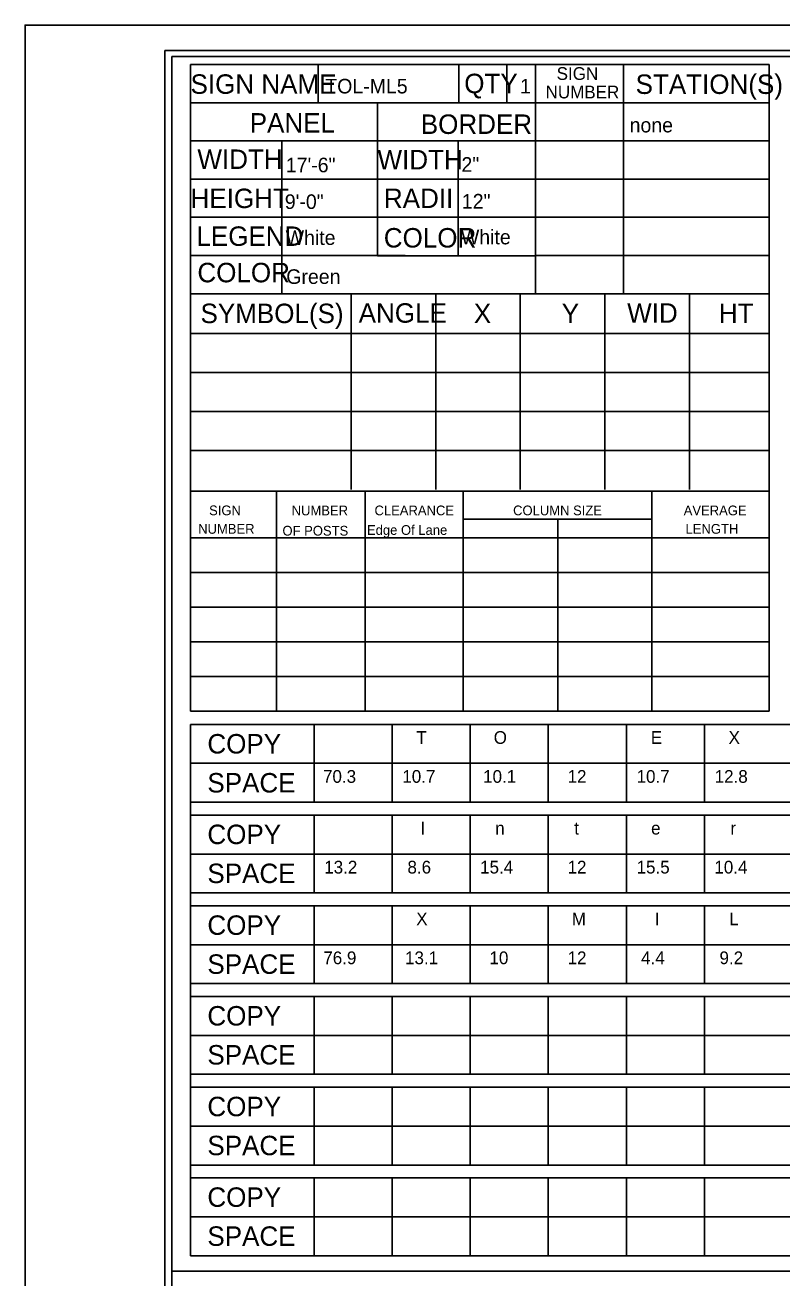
# Model space of a CAD drawing. Extents: x 122633 to 124574, y -23288 to -22025.
# Drawn here: x 122633 to 122983, y -22604 to -22025 of the extents above; entities that cross this region are included whole.
import ezdxf

# ---------------------------------------------------------------- set-up
doc = ezdxf.new("R2010")
doc.units = 0
for name, color, linetype in [('GSSign', 7, 'Continuous'), ('PlotBorder_dp', 7, 'Continuous'), ('SheetBorder_dp', 7, 'Continuous'), ('SheetLinesMisc2_dp', 7, 'Continuous'), ('TextMinor', 7, 'Continuous')]:
    doc.layers.add(name, color=color, linetype=linetype)

msp = doc.modelspace()

# ---------------------------------------------------------------- linework, layer by layer
at = {"layer": 'PlotBorder_dp'}
msp.add_lwpolyline([(122633.11, -23271.62), (124574.11, -23271.62), (124574.11, -22024.68), (122633.11, -22024.68)], close=True, dxfattribs=at)
at = {"layer": 'SheetBorder_dp'}
for q in [(124509.41, -22036.45), (122697.81, -23259.86)]:
    msp.add_line((122697.81, -22036.45), q, dxfattribs=at)
at = {"layer": 'SheetLinesMisc2_dp'}
for p, q in [((122701.01, -22039.22), (124506.26, -22039.22)), ((122701.01, -22039.22), (122701.01, -23162.98)), ((122709.67, -22342.04), (122709.67, -22042.97)), ((122709.67, -22042.97), (122977.34, -22042.97)), ((122768.68, -22042.97), (122768.68, -22060.63)), ((122833.74, -22042.97), (122833.74, -22060.63)), ((122855.97, -22042.97), (122855.97, -22060.63)), ((122869.21, -22042.97), (122869.21, -22148.96)), ((122909.94, -22042.97), (122909.94, -22148.96)), ((122977.34, -22042.97), (122977.34, -22342.04)), ((122709.67, -22060.63), (122977.34, -22060.63)), ((122796.18, -22060.63), (122796.18, -22131.48)), ((122709.67, -22078.3), (122977.34, -22078.3)), ((122751.97, -22078.3), (122751.97, -22148.96)), ((122833.51, -22078.49), (122833.51, -22131.48)), ((122709.67, -22095.97), (122977.34, -22095.97)), ((122709.67, -22113.63), (122977.34, -22113.63)), ((122709.67, -22131.3), (122808.94, -22131.3)), ((122796.18, -22131.48), (122869.21, -22131.48)), ((122869.21, -22131.3), (122977.34, -22131.3)), ((122709.67, -22148.96), (122977.34, -22148.96)), ((122784.01, -22149.31), (122784.01, -22239.5)), ((122823.12, -22149.31), (122823.12, -22239.5)), ((122862.23, -22149.31), (122862.23, -22239.5)), ((122901.34, -22149.31), (122901.34, -22239.5)), ((122940.45, -22149.31), (122940.45, -22239.5)), ((122709.73, -22167.35), (122977.34, -22167.35)), ((122709.73, -22185.39), (122977.34, -22185.39)), ((122709.73, -22203.42), (122977.34, -22203.42)), ((122709.73, -22221.46), (122977.34, -22221.46)), ((122709.67, -22240.36), (122977.34, -22240.36)), ((122749.39, -22240.36), (122749.39, -22342.04)), ((122790.45, -22240.36), (122790.45, -22342.04)), ((122835.78, -22240.36), (122835.78, -22342.04)), ((122923.07, -22240.36), (122923.07, -22342.04)), ((122835.78, -22253.29), (122923.01, -22253.29)), ((122879.6, -22253.29), (122879.6, -22342.04)), ((122709.67, -22261.92), (122977.34, -22261.92)), ((122709.67, -22277.94), (122977.34, -22277.94)), ((122709.67, -22293.97), (122977.34, -22293.97)), ((122709.67, -22309.99), (122977.34, -22309.99)), ((122709.67, -22326.01), (122977.34, -22326.01)), ((122709.67, -22342.04), (122977.34, -22342.04)), ((122709.67, -22348.2), (123597.5, -22348.2)), ((122709.67, -22594.02), (122709.67, -22348.2)), ((122766.82, -22348.2), (122766.82, -22384.27)), ((122802.94, -22348.2), (122802.94, -22384.27)), ((122839.06, -22348.2), (122839.06, -22384.27)), ((122875.17, -22348.2), (122875.17, -22384.27)), ((122911.28, -22348.2), (122911.28, -22384.27)), ((122947.4, -22348.2), (122947.4, -22384.27)), ((122709.67, -22366.23), (123597.5, -22366.23)), ((122709.67, -22384.27), (123597.5, -22384.27)), ((122709.67, -22390.15), (123597.5, -22390.15)), ((122766.82, -22390.15), (122766.82, -22426.22)), ((122802.94, -22390.15), (122802.94, -22426.22)), ((122839.06, -22390.15), (122839.06, -22426.22)), ((122875.17, -22390.15), (122875.17, -22426.22)), ((122911.28, -22390.15), (122911.28, -22426.22)), ((122947.4, -22390.15), (122947.4, -22426.22)), ((122709.67, -22408.19), (123597.5, -22408.18)), ((122709.67, -22426.22), (123597.5, -22426.22)), ((122709.67, -22432.1), (123597.5, -22432.1)), ((122766.82, -22432.1), (122766.82, -22468.17)), ((122802.94, -22432.1), (122802.94, -22468.17)), ((122839.06, -22432.1), (122839.06, -22468.17)), ((122875.17, -22432.1), (122875.17, -22468.17)), ((122911.28, -22432.1), (122911.28, -22468.17)), ((122947.4, -22432.1), (122947.4, -22468.17)), ((122709.67, -22450.14), (123597.5, -22450.14)), ((122709.67, -22468.17), (123597.5, -22468.17)), ((122709.67, -22474.05), (123597.5, -22474.05)), ((122766.82, -22474.05), (122766.82, -22510.12)), ((122802.94, -22474.05), (122802.94, -22510.12)), ((122839.06, -22474.05), (122839.06, -22510.12)), ((122875.17, -22474.05), (122875.17, -22510.12)), ((122911.28, -22474.05), (122911.28, -22510.12)), ((122947.4, -22474.05), (122947.4, -22510.12)), ((122709.67, -22492.09), (123597.5, -22492.09)), ((122709.67, -22510.12), (123597.5, -22510.12)), ((122709.67, -22516.01), (123597.5, -22516.01)), ((122766.82, -22516.01), (122766.82, -22552.08)), ((122802.94, -22516.01), (122802.94, -22552.08)), ((122839.06, -22516.01), (122839.06, -22552.08)), ((122875.17, -22516.01), (122875.17, -22552.08)), ((122911.28, -22516.01), (122911.28, -22552.08)), ((122947.4, -22516.01), (122947.4, -22552.08)), ((122709.67, -22534.04), (123597.5, -22534.04)), ((122709.67, -22552.08), (123597.5, -22552.08)), ((122709.67, -22557.96), (123597.5, -22557.96)), ((122766.82, -22557.96), (122766.82, -22594.02)), ((122802.94, -22557.96), (122802.94, -22594.02)), ((122839.06, -22557.96), (122839.06, -22594.02)), ((122875.17, -22557.96), (122875.17, -22594.02)), ((122911.28, -22557.96), (122911.28, -22594.02)), ((122947.4, -22557.96), (122947.4, -22594.02)), ((122709.67, -22575.98), (123597.5, -22575.98)), ((122709.67, -22594.02), (123597.5, -22594.02)), ((122701.01, -22601.11), (124506.26, -22601.11))]:
    msp.add_line(p, q, dxfattribs=at)

# ---------------------------------------------------------------- texts
at = {"layer": 'GSSign'}
for s, height, p in [('TOL-ML5', 6.749, (122772, -22056.32)), ('1', 6.75, (122862.09, -22056.33)), ('none', 6.749, (122912.8, -22074.34)), ('17\'-6"', 6.749, (122753.74, -22092.8)), ('2"', 6.749, (122835.01, -22092.55)), ('9\'-0"', 6.749, (122753.28, -22109.76)), ('12"', 6.749, (122835.19, -22109.57)), ('White', 6.749, (122753.67, -22126.4)), ('White', 6.749, (122834.73, -22126.14)), ('Green', 6.749, (122753.96, -22144.44)), ('T', 5.88, (122814.08, -22357.22)), ('O', 5.88, (122849.92, -22357.22)), ('E', 5.88, (122922.59, -22357.22)), ('X', 5.88, (122958.58, -22357.22)), ('70.3', 5.882, (122770.95, -22375.25)), ('10.7', 5.882, (122807.64, -22375.25)), ('10.1', 5.882, (122845.02, -22375.25)), ('12', 5.882, (122884.09, -22375.25)), ('10.7', 5.882, (122916.01, -22375.25)), ('12.8', 5.882, (122952.14, -22375.25)), ('I', 5.88, (122816.04, -22399.17)), ('n', 5.88, (122850.62, -22399.17)), ('t', 5.88, (122887.17, -22399.17)), ('e', 5.88, (122922.73, -22399.17)), ('r', 5.88, (122959.42, -22399.17)), ('13.2', 5.882, (122771.51, -22417.21)), ('8.6', 5.882, (122810.02, -22417.21)), ('15.4', 5.882, (122843.62, -22417.21)), ('12', 5.882, (122884.09, -22417.21)), ('15.5', 5.882, (122916.01, -22417.21)), ('10.4', 5.882, (122952, -22417.21)), ('X', 5.88, (122814.08, -22441.13)), ('M', 5.88, (122886.05, -22441.13)), ('I', 5.88, (122924.41, -22441.13)), ('L', 5.88, (122958.86, -22441.13)), ('76.9', 5.882, (122771.09, -22459.16)), ('13.1', 5.882, (122808.9, -22459.16)), ('10', 5.882, (122847.96, -22459.16)), ('12', 5.882, (122884.09, -22459.16)), ('4.4', 5.882, (122918.11, -22459.16)), ('9.2', 5.882, (122954.38, -22459.16))]:
    msp.add_text(s, height=height, dxfattribs=at).set_placement(p)
at = {"layer": 'TextMinor'}
for s, height, p in [('SIGN NAME', 8.999, (122709.67, -22056.49)), ('QTY', 8.999, (122836.3, -22056.2)), ('SIGN', 5.882, (122879.04, -22050.05)), ('STATION(S)', 8.999, (122915.56, -22056.55)), ('NUMBER', 5.882, (122873.93, -22058.61)), ('PANEL', 8.999, (122737.04, -22074.44)), ('BORDER', 8.999, (122816.19, -22075.05)), ('WIDTH', 8.999, (122712.85, -22091.25)), ('WIDTH', 8.999, (122796.18, -22091.44)), ('HEIGHT', 8.999, (122709.67, -22109.36)), ('RADII', 8.999, (122799.13, -22109.33)), ('LEGEND', 8.999, (122712.38, -22126.84)), ('COLOR', 8.999, (122799.07, -22127.6)), ('COLOR', 8.999, (122712.85, -22143.69)), ('SYMBOL(S)', 8.999, (122714.28, -22162.57)), ('ANGLE', 8.999, (122787.45, -22162.39)), ('X', 9, (122840.72, -22162.57)), ('Y', 9, (122881.39, -22162.57)), ('WID', 8.999, (122911.67, -22162.39)), ('HT', 8.999, (122954.07, -22162.56)), ('SIGN', 4.5, (122718.25, -22251.46)), ('NUMBER', 4.5, (122756.45, -22251.52)), ('CLEARANCE', 4.5, (122794.77, -22251.48)), ('COLUMN SIZE', 4.4996, (122858.89, -22251.48)), ('AVERAGE', 4.5, (122937.81, -22251.48)), ('NUMBER', 4.5, (122713.21, -22260.02)), ('OF POSTS', 4.5, (122752.2, -22260.87)), ('Edge Of Lane', 4.4996, (122791.3, -22260.54)), ('LENGTH', 4.5, (122938.66, -22260.02)), ('COPY', 8.999, (122717.46, -22361.69)), ('SPACE', 8.999, (122717.46, -22379.73)), ('COPY', 8.999, (122717.46, -22403.6)), ('SPACE', 8.999, (122717.46, -22421.64)), ('COPY', 8.999, (122717.46, -22445.59)), ('SPACE', 8.999, (122717.46, -22463.63)), ('COPY', 8.999, (122717.46, -22487.54)), ('SPACE', 8.999, (122717.46, -22505.58)), ('COPY', 8.999, (122717.46, -22529.5)), ('SPACE', 8.999, (122717.46, -22547.54)), ('COPY', 8.999, (122717.46, -22571.43)), ('SPACE', 8.999, (122717.46, -22589.47))]:
    msp.add_text(s, height=height, dxfattribs=at).set_placement(p)

doc.saveas('drawing.dxf')
